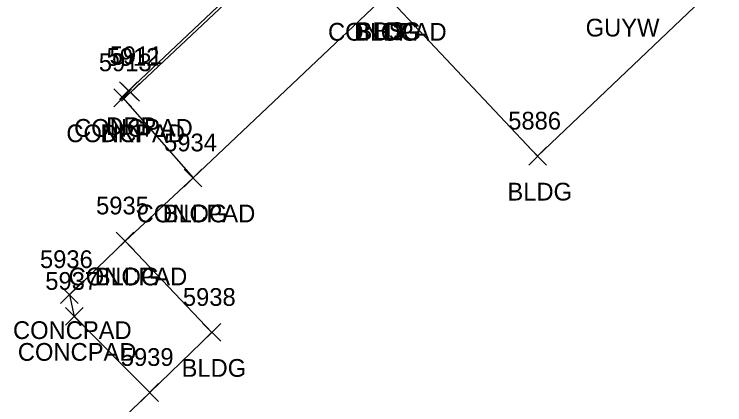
# Model space of a CAD drawing. Extents: x 1618146 to 1620418, y 640749 to 641927.
# Drawn here: x 1620002.4 to 1620082.5, y 641136.7 to 641180.8 of the extents above; entities that cross this region are included whole.
import ezdxf

# ---------------------------------------------------------------- set-up
doc = ezdxf.new("R2010")
doc.units = 0
for name, color, linetype in [('L_A', 7, 'Continuous'), ('L_I', 7, 'Continuous'), ('L_TIC', 7, 'Continuous'), ('LBC', 7, 'Continuous'), ('LS', 7, 'Continuous'), ('R_A', 7, 'Continuous'), ('R_I', 7, 'Continuous'), ('R_TIC', 7, 'Continuous'), ('RDP', 7, 'Continuous'), ('U_A', 7, 'Continuous')]:
    doc.layers.add(name, color=color, linetype=linetype)

msp = doc.modelspace()

# ---------------------------------------------------------------- linework, layer by layer
at = {"layer": 'L_TIC'}
for points in [[(1620014.554, 641170.939), (1620016.554, 641172.939)], [(1620016.554, 641170.939), (1620014.554, 641172.939)], [(1620013.678, 641170.33), (1620015.678, 641172.33)], [(1620015.678, 641170.33), (1620013.678, 641172.33)], [(1620060.444, 641163.754), (1620062.444, 641165.754)], [(1620062.444, 641163.754), (1620060.444, 641165.754)], [(1620021.603, 641161.294), (1620023.603, 641163.294)], [(1620023.603, 641161.294), (1620021.603, 641163.294)], [(1620021.603, 641161.294), (1620023.603, 641163.294)], [(1620023.603, 641161.294), (1620021.603, 641163.294)], [(1620013.935, 641154.186), (1620015.935, 641156.186)], [(1620015.935, 641154.186), (1620013.935, 641156.186)], [(1620013.935, 641154.186), (1620015.935, 641156.186)], [(1620015.935, 641154.186), (1620013.935, 641156.186)], [(1620007.666, 641148.138), (1620009.666, 641150.138)], [(1620009.666, 641148.138), (1620007.666, 641150.138)], [(1620008.211, 641145.685), (1620010.211, 641147.685)], [(1620010.211, 641145.685), (1620008.211, 641147.685)], [(1620023.72, 641143.878), (1620025.72, 641145.878)], [(1620025.72, 641143.878), (1620023.72, 641145.878)], [(1620016.727, 641137.107), (1620018.727, 641139.107)], [(1620018.727, 641137.107), (1620016.727, 641139.107)], [(1620016.727, 641137.107), (1620018.727, 641139.107)], [(1620018.727, 641137.107), (1620016.727, 641139.107)]]:
    msp.add_lwpolyline(points, dxfattribs=at)
at = {"layer": 'LBC'}
msp.add_lwpolyline([(1620182.251, 641113.365), (1620138.873, 641158.876), (1620119.634, 641179.081), (1620099.137, 641200.676), (1620061.444, 641164.754), (1620044.431, 641182.84), (1620044.169, 641182.771), (1620022.603, 641162.294), (1620014.935, 641155.186), (1620024.72, 641144.878), (1620017.727, 641138.107), (1620002.991, 641123.903), (1620002.581, 641122.317), (1620005.727, 641115.216)], dxfattribs=at)
at = {"layer": 'LS'}
for points in [[(1620044.169, 641182.771), (1620036.207, 641191.402), (1620015.554, 641171.939), (1620014.678, 641171.33), (1620022.603, 641162.294)], [(1620014.935, 641155.186), (1620008.666, 641149.138), (1620009.211, 641146.685), (1620017.727, 641138.107)]]:
    msp.add_lwpolyline(points, dxfattribs=at)
at = {"layer": 'R_TIC'}
for points in [[(1620014.329, 641171.126), (1620016.329, 641173.126)], [(1620016.329, 641171.126), (1620014.329, 641173.126)], [(1620013.678, 641170.33), (1620015.678, 641172.33)], [(1620015.678, 641170.33), (1620013.678, 641172.33)]]:
    msp.add_lwpolyline(points, dxfattribs=at)
at = {"layer": 'RDP'}
msp.add_lwpolyline([(1620043.034, 641194.193), (1620036.085, 641191.731), (1620015.329, 641172.126), (1620014.678, 641171.33)], dxfattribs=at)

# ---------------------------------------------------------------- texts
at = {"layer": 'L_A'}
for s, p in [('CONCPAD', (1620037.815, 641177.771)), ('BLDG', (1620040.76, 641177.771)), ('BLDG', (1620041.022, 641177.84)), ('BS', (1620042.872, 641177.84)), ('CONCPAD', (1620009.2, 641166.939)), ('CONCPAD', (1620008.324, 641166.33)), ('BLDG', (1620058.035, 641159.754)), ('CONCPAD', (1620016.249, 641157.294)), ('BLDG', (1620019.194, 641157.294)), ('CONCPAD', (1620008.58, 641150.186)), ('BLDG', (1620011.525, 641150.186)), ('CONCPAD', (1620002.311, 641144.138)), ('CONCPAD', (1620002.856, 641141.685)), ('BLDG', (1620021.31, 641139.878))]:
    msp.add_text(s, height=2, dxfattribs=at).set_placement(p)
at = {"layer": 'L_I'}
for s, p in [('5912', (1620012.862, 641174.939)), ('5913', (1620011.985, 641174.33)), ('5886', (1620058.129, 641167.754)), ('5934', (1620019.343, 641165.294)), ('5934', (1620019.343, 641165.294)), ('5935', (1620011.675, 641158.186)), ('5935', (1620011.675, 641158.186)), ('5936', (1620005.351, 641152.138)), ('5937', (1620005.951, 641149.685)), ('5938', (1620021.46, 641147.878)), ('5939', (1620014.459, 641141.107)), ('5939', (1620014.459, 641141.107))]:
    msp.add_text(s, height=2, dxfattribs=at).set_placement(p)
at = {"layer": 'R_A'}
for p in [(1620012.817, 641167.126), (1620012.166, 641166.33)]:
    msp.add_text('DRP', height=2, dxfattribs=at).set_placement(p)
at = {"layer": 'R_I'}
for s, p in [('5911', (1620013.203, 641175.126)), ('5913', (1620011.985, 641174.33))]:
    msp.add_text(s, height=2, dxfattribs=at).set_placement(p)
at = {"layer": 'U_A'}
msp.add_text('GUYW', height=2, dxfattribs=at).set_placement((1620066.854, 641178.243))

doc.saveas('drawing.dxf')
